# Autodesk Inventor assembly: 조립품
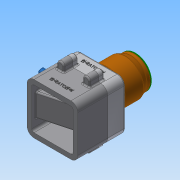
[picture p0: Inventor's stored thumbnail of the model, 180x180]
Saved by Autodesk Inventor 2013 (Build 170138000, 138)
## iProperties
Created: 2018-01
Part Number: 조립품
Document SubType Name: Assembly
Designer: Administrator
Author: Administrator
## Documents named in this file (9)
- C:\Users\Administrator\Desktop\480108V1029\조립품.iam
- C:\Users\Administrator\Desktop\480108V1029\480108V1029.ipt
- C:\Users\Administrator\Desktop\480108V1029\핸들축.ipt
- C:\Users\Administrator\Desktop\480108V1029\핸들.ipt
- C:\Users\Administrator\Desktop\480108V1029\볼트 M3x12.ipt
- C:\Users\Administrator\Desktop\480108V1029\본체커버.ipt
- C:\Users\Administrator\Desktop\480108V1029\볼트 M4x12.ipt
- C:\Users\Administrator\Desktop\480108V1029\용기.ipt
- C:\Users\Administrator\Desktop\480108V1029\용기캡.ipt
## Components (3 placed, 3 different names)
1. 480108V1029:1
2. 핸들축:1
3. 핸들:1
